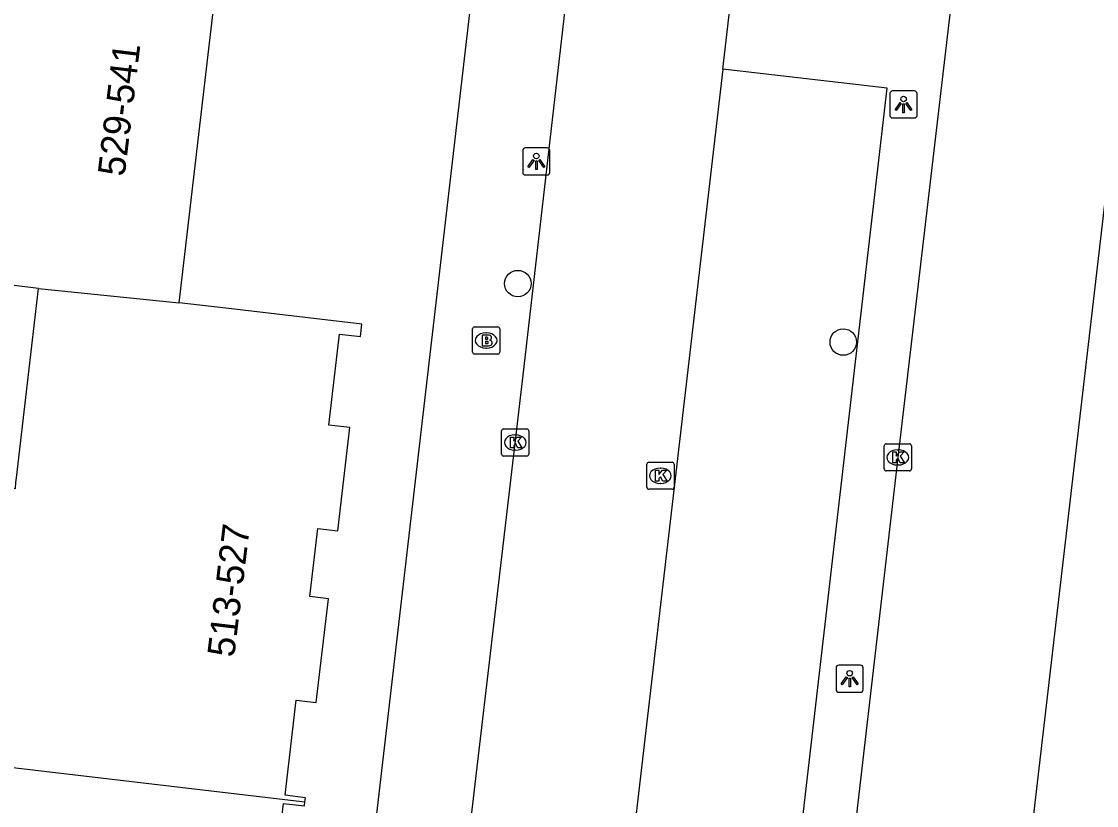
# Model space of a CAD drawing. Extents: x 160861 to 161308, y 384024 to 384878.
# Drawn here: x 161224.9 to 161264.5, y 384529.61 to 384558.5 of the extents above; entities that cross this region are included whole.
import ezdxf

# ---------------------------------------------------------------- set-up
doc = ezdxf.new("R2010")
doc.units = 0
for name, color, linetype in [('IMGEO_Boom', 7, 'Continuous'), ('IMGEO_Brandkraan', 7, 'Continuous'), ('IMGEO_Kolk', 7, 'Continuous'), ('IMGEO_Lichtpunt', 7, 'Continuous'), ('IMGEO_Pand', 7, 'Continuous'), ('IMGEO_Pand_nummerreeks', 7, 'Continuous'), ('IMGEO_Parkeervlak_open', 7, 'Continuous'), ('IMGEO_Rijbaan_lokaal_gesloten', 7, 'Continuous'), ('IMGEO_Rijbaan_lokaal_open', 7, 'Continuous'), ('IMGEO_Voetpad_open', 7, 'Continuous')]:
    doc.layers.add(name, color=color, linetype=linetype)

msp = doc.modelspace()

# ---------------------------------------------------------------- linework, layer by layer
at = {"layer": 'IMGEO_Boom'}
for centre in [(161243.181, 384548.842), (161255.169, 384546.689)]:
    msp.add_circle(centre, 0.489, dxfattribs=at)
at = {"layer": 'IMGEO_Brandkraan'}
for p, q in [((161241.516, 384546.322), (161241.516, 384547.174)), ((161241.591, 384547.248), (161242.443, 384547.248)), ((161242.517, 384547.174), (161242.517, 384546.322)), ((161242.004, 384547.028), (161242.029, 384547.028)), ((161242.027, 384546.468), (161242.002, 384546.468)), ((161242.443, 384546.248), (161241.591, 384546.248))]:
    msp.add_line(p, q, dxfattribs=at)
for points in [[(161241.516, 384546.322), (161241.516, 384547.174)], [(161241.591, 384547.248), (161242.443, 384547.248)], [(161242.517, 384547.174), (161242.517, 384546.322)], [(161241.864, 384546.948), (161241.864, 384546.548), (161242.077, 384546.548)], [(161242.095, 384546.948), (161241.864, 384546.948)], [(161242.043, 384546.867), (161241.989, 384546.867), (161241.989, 384546.791)], [(161241.989, 384546.791), (161242.042, 384546.791)], [(161242.051, 384546.715), (161241.989, 384546.715), (161241.989, 384546.634)], [(161241.989, 384546.634), (161242.051, 384546.634)], [(161242.443, 384546.248), (161241.591, 384546.248)]]:
    msp.add_lwpolyline(points, dxfattribs=at)
for centre, radius, start, end in [((161241.593, 384547.172), 0.0765, 91.552, 178.448), ((161241.593, 384547.172), 0.0765, 91.552, 178.448), ((161242.441, 384547.172), 0.0765, 1.552, 88.448), ((161242.441, 384547.172), 0.0765, 1.552, 88.448), ((161242.044, 384546.829), 0.0379, 267.8285, 90.9355), ((161242.099, 384546.803), 0.145, 59.4692, 91.5367), ((161242.124, 384546.85), 0.0922, 285.5137, 58.1501), ((161242.052, 384546.674), 0.0404, 269.8759, 90.5077), ((161242.083, 384546.799), 0.251, 268.6676, 293.5347), ((161242.129, 384546.658), 0.105, 301.3115, 78.989), ((161241.593, 384546.324), 0.0765, 181.552, 268.448), ((161241.593, 384546.324), 0.0765, 181.552, 268.448), ((161242.441, 384546.324), 0.0765, 271.552, 358.448), ((161242.441, 384546.324), 0.0765, 271.552, 358.448)]:
    msp.add_arc(centre, radius, start, end, dxfattribs=at)
for centre, major_axis, ratio, start_param, end_param in [((161242.003, 384546.748), (-0.387, 0.002), 0.722429, 4.712389, 7.853982), ((161242.028, 384546.748), (-0.39, 0.002), 0.717154, 1.570796, 4.712389)]:
    msp.add_ellipse(centre, major_axis=major_axis, ratio=ratio, start_param=start_param, end_param=end_param, dxfattribs=at)
at = {"layer": 'IMGEO_Kolk'}
for p, q in [((161242.586, 384542.56), (161242.586, 384543.412)), ((161242.661, 384543.486), (161243.513, 384543.486)), ((161243.074, 384543.266), (161243.099, 384543.266)), ((161243.587, 384543.412), (161243.587, 384542.56)), ((161256.677, 384542.013), (161256.677, 384542.865)), ((161256.752, 384542.939), (161257.604, 384542.939)), ((161257.678, 384542.865), (161257.678, 384542.013)), ((161243.513, 384542.486), (161242.661, 384542.486)), ((161243.097, 384542.706), (161243.072, 384542.706)), ((161257.165, 384542.719), (161257.19, 384542.719)), ((161247.934, 384541.337), (161247.934, 384542.189)), ((161248.009, 384542.263), (161248.861, 384542.263)), ((161248.422, 384542.043), (161248.447, 384542.043)), ((161248.935, 384542.189), (161248.935, 384541.337)), ((161257.188, 384542.159), (161257.163, 384542.159)), ((161257.604, 384541.939), (161256.752, 384541.939)), ((161248.861, 384541.263), (161248.009, 384541.263)), ((161248.445, 384541.483), (161248.42, 384541.483))]:
    msp.add_line(p, q, dxfattribs=at)
for points in [[(161242.586, 384542.56), (161242.586, 384543.412)], [(161242.661, 384543.486), (161243.513, 384543.486)], [(161243.587, 384543.412), (161243.587, 384542.56)], [(161242.907, 384543.186), (161243.03, 384543.186), (161243.03, 384543.035), (161243.16, 384543.186), (161243.324, 384543.186), (161243.178, 384543.035), (161243.331, 384542.786), (161243.179, 384542.786), (161243.094, 384542.95), (161243.03, 384542.883), (161243.03, 384542.786), (161242.907, 384542.786), (161242.907, 384543.186)], [(161256.677, 384542.013), (161256.677, 384542.865)], [(161256.752, 384542.939), (161257.604, 384542.939)], [(161257.678, 384542.865), (161257.678, 384542.013)], [(161243.513, 384542.486), (161242.661, 384542.486)], [(161256.998, 384542.639), (161257.121, 384542.639), (161257.121, 384542.488), (161257.251, 384542.639), (161257.415, 384542.639), (161257.269, 384542.488), (161257.422, 384542.239), (161257.27, 384542.239), (161257.185, 384542.403), (161257.121, 384542.336), (161257.121, 384542.239), (161256.998, 384542.239), (161256.998, 384542.639)], [(161247.934, 384541.337), (161247.934, 384542.189)], [(161248.009, 384542.263), (161248.861, 384542.263)], [(161248.935, 384542.189), (161248.935, 384541.337)], [(161248.255, 384541.963), (161248.378, 384541.963), (161248.378, 384541.812), (161248.508, 384541.963), (161248.672, 384541.963), (161248.526, 384541.812), (161248.679, 384541.563), (161248.527, 384541.563), (161248.442, 384541.727), (161248.378, 384541.66), (161248.378, 384541.563), (161248.255, 384541.563), (161248.255, 384541.963)], [(161257.604, 384541.939), (161256.752, 384541.939)], [(161248.861, 384541.263), (161248.009, 384541.263)]]:
    msp.add_lwpolyline(points, dxfattribs=at)
for centre, start, end in [((161242.663, 384543.41), 91.552, 178.448), ((161242.663, 384543.41), 91.552, 178.448), ((161243.511, 384543.41), 1.552, 88.448), ((161243.511, 384543.41), 1.552, 88.448), ((161256.754, 384542.863), 91.552, 178.448), ((161256.754, 384542.863), 91.552, 178.448), ((161257.602, 384542.863), 1.552, 88.448), ((161257.602, 384542.863), 1.552, 88.448), ((161242.663, 384542.562), 181.552, 268.448), ((161242.663, 384542.562), 181.552, 268.448), ((161243.511, 384542.562), 271.552, 358.448), ((161243.511, 384542.562), 271.552, 358.448), ((161248.011, 384542.187), 91.552, 178.448), ((161248.011, 384542.187), 91.552, 178.448), ((161248.859, 384542.187), 1.552, 88.448), ((161248.859, 384542.187), 1.552, 88.448), ((161256.754, 384542.015), 181.552, 268.448), ((161256.754, 384542.015), 181.552, 268.448), ((161257.602, 384542.015), 271.552, 358.448), ((161257.602, 384542.015), 271.552, 358.448), ((161248.011, 384541.339), 181.552, 268.448), ((161248.011, 384541.339), 181.552, 268.448), ((161248.859, 384541.339), 271.552, 358.448), ((161248.859, 384541.339), 271.552, 358.448)]:
    msp.add_arc(centre, 0.0765, start, end, dxfattribs=at)
for centre, major_axis, ratio, start_param, end_param in [((161243.073, 384542.986), (-0.387, 0.002), 0.722429, 4.712389, 7.853982), ((161243.098, 384542.986), (-0.39, 0.002), 0.717154, 1.570796, 4.712389), ((161257.164, 384542.439), (-0.387, 0.002), 0.722429, 4.712389, 7.853982), ((161257.189, 384542.439), (-0.39, 0.002), 0.717154, 1.570796, 4.712389), ((161248.421, 384541.763), (-0.387, 0.002), 0.722429, 4.712389, 7.853982), ((161248.446, 384541.763), (-0.39, 0.002), 0.717154, 1.570796, 4.712389)]:
    msp.add_ellipse(centre, major_axis=major_axis, ratio=ratio, start_param=start_param, end_param=end_param, dxfattribs=at)
at = {"layer": 'IMGEO_Lichtpunt'}
for p, q in [((161257.791, 384555.941), (161256.983, 384555.941)), ((161257.791, 384555.941), (161256.983, 384555.941)), ((161256.889, 384555.846), (161256.889, 384555.039)), ((161256.889, 384555.846), (161256.889, 384555.039)), ((161257.885, 384555.039), (161257.885, 384555.846)), ((161257.885, 384555.039), (161257.885, 384555.846)), ((161256.983, 384554.945), (161257.791, 384554.945)), ((161256.983, 384554.945), (161257.791, 384554.945)), ((161243.366, 384553.747), (161243.366, 384552.94)), ((161243.366, 384553.747), (161243.366, 384552.94)), ((161244.268, 384553.842), (161243.46, 384553.842)), ((161244.268, 384553.842), (161243.46, 384553.842)), ((161244.362, 384552.94), (161244.362, 384553.747)), ((161244.362, 384552.94), (161244.362, 384553.747)), ((161243.46, 384552.846), (161244.268, 384552.846)), ((161243.46, 384552.846), (161244.268, 384552.846)), ((161254.906, 384534.689), (161254.906, 384533.882)), ((161254.906, 384534.689), (161254.906, 384533.882)), ((161255.808, 384534.784), (161255, 384534.784)), ((161255.808, 384534.784), (161255, 384534.784)), ((161255.902, 384533.882), (161255.902, 384534.689)), ((161255.902, 384533.882), (161255.902, 384534.689)), ((161255, 384533.788), (161255.808, 384533.788)), ((161255, 384533.788), (161255.808, 384533.788))]:
    msp.add_line(p, q, dxfattribs=at)
for points in [[(161257.263, 384555.51), (161257.302, 384555.482), (161257.114, 384555.22), (161257.076, 384555.247), (161257.263, 384555.51)], [(161257.475, 384555.482), (161257.513, 384555.509), (161257.7, 384555.247), (161257.661, 384555.219), (161257.475, 384555.482)], [(161257.365, 384555.462), (161257.412, 384555.462), (161257.412, 384555.14), (161257.365, 384555.14), (161257.365, 384555.462)], [(161243.74, 384553.411), (161243.779, 384553.383), (161243.591, 384553.121), (161243.553, 384553.148), (161243.74, 384553.411)], [(161243.842, 384553.363), (161243.889, 384553.363), (161243.889, 384553.041), (161243.842, 384553.041), (161243.842, 384553.363)], [(161243.952, 384553.383), (161243.99, 384553.41), (161244.177, 384553.148), (161244.138, 384553.12), (161243.952, 384553.383)], [(161255.28, 384534.353), (161255.319, 384534.325), (161255.131, 384534.063), (161255.093, 384534.09), (161255.28, 384534.353)], [(161255.382, 384534.305), (161255.429, 384534.305), (161255.429, 384533.983), (161255.382, 384533.983), (161255.382, 384534.305)], [(161255.492, 384534.325), (161255.53, 384534.352), (161255.717, 384534.09), (161255.678, 384534.062), (161255.492, 384534.325)]]:
    msp.add_lwpolyline(points, dxfattribs=at)
for centre in [(161257.388, 384555.644), (161243.865, 384553.545), (161255.405, 384534.487)]:
    msp.add_circle(centre, 0.0994, dxfattribs=at)
for centre, start, end in [((161256.983, 384555.846), 90, 180), ((161256.983, 384555.846), 90, 180), ((161257.791, 384555.846), 0, 90), ((161257.791, 384555.846), 0, 90), ((161256.983, 384555.039), 180, 270), ((161256.983, 384555.039), 180, 270), ((161257.791, 384555.039), 270, 0), ((161257.791, 384555.039), 270, 360), ((161243.46, 384553.747), 90, 180), ((161243.46, 384553.747), 90, 180), ((161244.268, 384553.747), 0, 90), ((161244.268, 384553.747), 0, 90), ((161243.46, 384552.94), 180, 270), ((161243.46, 384552.94), 180, 270), ((161244.268, 384552.94), 270, 0), ((161244.268, 384552.94), 270, 360), ((161255, 384534.689), 90, 180), ((161255, 384534.689), 90, 180), ((161255.808, 384534.689), 0, 90), ((161255.808, 384534.689), 0, 90), ((161255, 384533.882), 180, 270), ((161255, 384533.882), 180, 270), ((161255.808, 384533.882), 270, 0), ((161255.808, 384533.882), 270, 360)]:
    msp.add_arc(centre, 0.0946, start, end, dxfattribs=at)
at = {"layer": 'IMGEO_Pand'}
for points in [[(161225.533, 384548.667), (161223.624, 384548.891), (161223.52, 384548.001), (161221.688, 384548.215), (161221.799, 384549.171), (161220.972, 384549.268), (161221.016, 384549.64), (161221.66, 384549.565), (161221.906, 384551.675), (161221.133, 384551.765), (161222.192, 384560.826), (161222.989, 384560.733), (161223.236, 384562.851), (161222.433, 384562.945), (161222.482, 384563.366), (161223.433, 384563.255), (161223.527, 384564.055), (161225.384, 384563.838), (161225.291, 384563.038), (161227.162, 384562.819), (161227.455, 384565.319), (161229.097, 384565.127), (161229.684, 384570.142)], [(161230.709, 384548.137), (161232.592, 384564.236), (161234.585, 384564.003), (161236.262, 384564.139), (161236.297, 384564.442), (161241.773, 384564.828), (161241.744, 384564.577), (161242.07, 384564.539)], [(161223.524, 384531.132), (161224.387, 384538.506), (161222.958, 384538.674), (161222.792, 384538.693), (161221.75, 384538.815), (161221.131, 384539.643), (161221.264, 384540.699), (161222.067, 384541.519), (161222.196, 384541.508), (161224.679, 384541.297), (161224.697, 384541.516), (161224.717, 384541.685), (161225.533, 384548.667)], [(161225.533, 384548.667), (161230.709, 384548.137)], [(161235.341, 384529.749), (161235.359, 384529.901), (161234.613, 384529.988), (161235.024, 384533.494), (161235.756, 384533.408), (161236.204, 384537.232), (161235.524, 384537.311), (161235.817, 384539.821), (161236.552, 384539.735), (161236.996, 384543.537), (161236.224, 384543.627), (161236.617, 384546.979), (161237.389, 384546.889), (161237.443, 384547.35), (161232.751, 384547.898), (161230.709, 384548.137)], [(161223.524, 384531.132), (161235.341, 384529.749)], [(161233.452, 384512.379), (161233.472, 384512.552), (161232.635, 384512.65), (161233.034, 384516.064), (161233.741, 384515.981), (161234.189, 384519.804), (161233.511, 384519.883), (161233.803, 384522.382), (161234.536, 384522.296), (161234.975, 384526.042), (161234.137, 384526.139), (161234.553, 384529.688), (161235.324, 384529.598), (161235.341, 384529.749)]]:
    msp.add_lwpolyline(points, dxfattribs=at)
at = {"layer": 'IMGEO_Parkeervlak_open'}
msp.add_lwpolyline([(161236.799, 384395.17), (161238.006, 384395.04), (161238.15, 384396.266), (161250.377, 384500), (161251.596, 384511.132), (161256.785, 384556.041), (161250.737, 384556.74)], dxfattribs=at)
at = {"layer": 'IMGEO_Rijbaan_lokaal_gesloten'}
for points in [[(161261.966, 384583.337), (161261.579, 384580.114), (161259.33, 384560.777), (161257.178, 384542.439), (161254.83, 384522.177), (161252.438, 384501.823), (161250.03, 384480.998), (161247.876, 384462.682), (161246.021, 384446.828), (161243.88, 384428.499), (161241.912, 384411.162), (161239.6, 384390.894), (161238.653, 384382.516), (161238.178, 384378.283), (161237.763, 384375.367), (161237.563, 384374.434), (161237.479, 384374.076), (161237.25, 384373.157), (161237.241, 384373.124)], [(161245.611, 384386.656), (161254.88, 384466.32), (161259.354, 384504.899), (161266.33, 384564.879), (161266.816, 384568.826), (161267.446, 384572.759), (161268.148, 384576.401), (161269.166, 384580.645)]]:
    msp.add_lwpolyline(points, dxfattribs=at)
at = {"layer": 'IMGEO_Rijbaan_lokaal_open'}
for points in [[(161237.656, 384495.995), (161237.777, 384496.96), (161238.057, 384500), (161239.778, 384514.805), (161243.381, 384545.472), (161249.855, 384601.831), (161250.766, 384609.622), (161253.738, 384634.519), (161253.842, 384635.509)], [(161250.737, 384556.74), (161251.303, 384561.613)], [(161250.737, 384556.74), (161231.686, 384393.141)]]:
    msp.add_lwpolyline(points, dxfattribs=at)
at = {"layer": 'IMGEO_Voetpad_open'}
msp.add_lwpolyline([(161242.07, 384564.539), (161234.582, 384500), (161233.969, 384494.717)], dxfattribs=at)

# ---------------------------------------------------------------- texts
at = {"layer": 'IMGEO_Pand_nummerreeks'}
for s, rotation, p in [('529-541', 83.1731, (161228.699, 384552.765)), ('513-527', 83.1591, (161232.735, 384535.047))]:
    msp.add_text(s, height=1, rotation=rotation, dxfattribs=at).set_placement(p)

doc.saveas('drawing.dxf')
